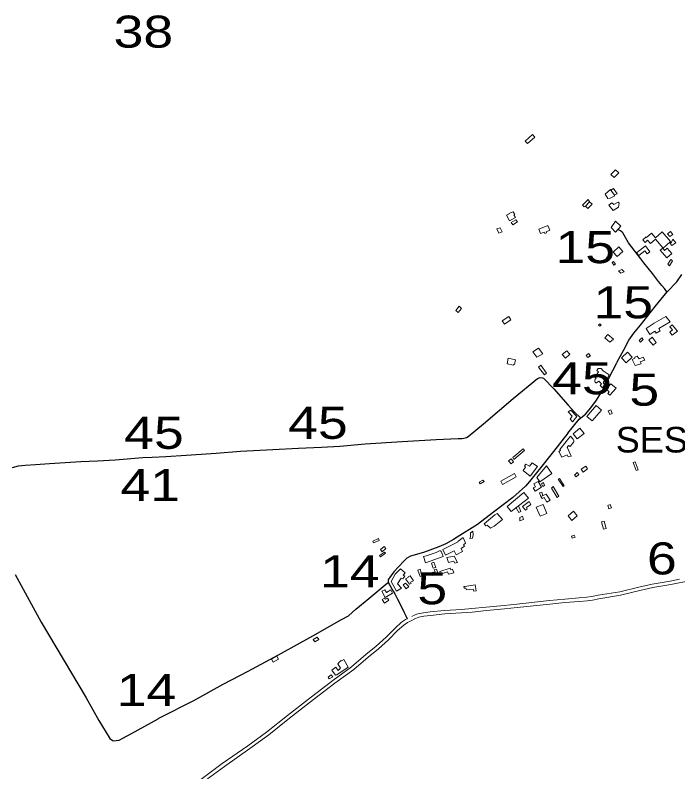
# Model space of a CAD drawing. Extents: x 476989 to 498418, y 4381813 to 4416555.
# Drawn here: x 484565 to 485599, y 4384627 to 4385808 of the extents above; entities that cross this region are included whole.
import ezdxf
from ezdxf.enums import TextEntityAlignment as Align

# ---------------------------------------------------------------- set-up
doc = ezdxf.new("R2010")
doc.units = 0
doc.header["$LTSCALE"] = 20
doc.linetypes.add('MEDIUM_DASHED', pattern=[4.5, 3, -1.5])
for name, color, linetype, lineweight in [('13', 7, 'Continuous', 13), ('36', 7, 'Continuous', 13), ('47', 7, 'Continuous', 13), ('48', 7, 'MEDIUM_DASHED', 13), ('6', 7, 'Continuous', 25)]:
    doc.layers.add(name, color=color, linetype=linetype, lineweight=lineweight)
doc.layers.add('7', color=7, linetype='Continuous')

msp = doc.modelspace()

# ---------------------------------------------------------------- linework, layer by layer
at = {"layer": '36'}
for points in [[(485422.62, 4384890.78), (485445.5, 4384892.7), (485457.67, 4384893.65), (485465.81, 4384894.8), (485475.68, 4384896.69), (485509.45, 4384902.29), (485539.74, 4384909.58), (485559.9, 4384914.32), (485587.94, 4384918.87), (485619.65, 4384925.47)], [(485422.69, 4384896.4), (485445.04, 4384898.28), (485457.06, 4384899.22), (485464.89, 4384900.34), (485474.69, 4384902.21), (485508.34, 4384907.79), (485538.44, 4384915.04), (485558.81, 4384919.82), (485586.93, 4384924.38), (485601.44, 4384927.38)], [(485183.89, 4384869.09), (485187.49, 4384870.96), (485193.57, 4384873.46), (485202.11, 4384874.97), (485212.4, 4384876.37), (485235.13, 4384878.7), (485261.36, 4384880.1), (485277.67, 4384881.57), (485300.11, 4384883.76), (485328.15, 4384886.54), (485347.71, 4384888.4), (485398.68, 4384894.02), (485422.69, 4384896.4)], [(484851.61, 4384605.75), (484891.48, 4384635.27), (484931.04, 4384662.95), (484960.7, 4384684.23), (484993.21, 4384710.28), (485030.75, 4384739.64), (485063.92, 4384764.85), (485093.47, 4384786.49), (485116.03, 4384805.54), (485131.93, 4384818.81), (485147.77, 4384832.69), (485161.73, 4384847.04), (485171.53, 4384855.86), (485177.07, 4384859.62), (485182.06, 4384861.97), (485189.79, 4384866.01), (485195.1, 4384868.19), (485202.95, 4384869.58), (485213.04, 4384870.95), (485235.55, 4384873.26), (485261.75, 4384874.66), (485278.18, 4384876.14), (485300.64, 4384878.33), (485328.67, 4384881.11), (485348.27, 4384882.97), (485399.25, 4384888.59), (485422.62, 4384890.78)], [(484707.31, 4384502.21), (484734.52, 4384522.99), (484765.58, 4384547.94), (484791.08, 4384567.66), (484812.71, 4384583.16), (484848.35, 4384610.12), (484888.3, 4384639.7), (484927.89, 4384667.41), (484957.41, 4384688.58), (484989.83, 4384714.56), (485027.43, 4384743.96), (485060.66, 4384769.23), (485090.09, 4384790.79), (485112.52, 4384809.73), (485128.38, 4384822.96), (485144.01, 4384836.66), (485157.94, 4384850.98), (485168.16, 4384860.16), (485174.35, 4384864.37), (485176.85, 4384865.55)]]:
    msp.add_lwpolyline(points, dxfattribs=at)
at = {"layer": '47'}
for p, q in [((485430.73, 4385278.66), (485429.6, 4385277.65)), ((485429.64, 4385279.89), (485430.73, 4385278.66)), ((485431.59, 4385150.48), (485427.01, 4385144.68))]:
    msp.add_line(p, q, dxfattribs=at)
for points in [[(485375.86, 4385617.36), (485364.42, 4385607.2), (485360.77, 4385611.28), (485372.16, 4385621.45)], [(485501.94, 4385566.31), (485494.71, 4385558.99), (485499.66, 4385554.11), (485506.89, 4385561.43)], [(485500.76, 4385525.8), (485493.57, 4385522.16), (485490.11, 4385521.53), (485485.71, 4385528.5), (485494.07, 4385535.43)], [(485461.45, 4385516.54), (485454.91, 4385509.66), (485458.68, 4385506.07), (485465.22, 4385512.95)], [(485491.39, 4385511.08), (485498.17, 4385502.8), (485506.43, 4385508.01), (485507.49, 4385514.15), (485506.17, 4385515.97), (485499.43, 4385512.02), (485496.02, 4385514.62)], [(485336.5, 4385486.96), (485331.77, 4385495.38), (485335.76, 4385497.44), (485335.29, 4385498.25), (485342.2, 4385500.73), (485344.58, 4385496.66), (485343.21, 4385496.15), (485345.76, 4385492.09)], [(485346.38, 4385488.49), (485348.86, 4385485.12), (485341.52, 4385480.52), (485338.96, 4385484.25)], [(485501.99, 4385486.17), (485494.94, 4385476.06), (485501.89, 4385468.84), (485509.91, 4385478.63)], [(485316.66, 4385474.25), (485319.79, 4385467.3), (485324.91, 4385469.72), (485321.65, 4385475.92)], [(485382.2, 4385473.84), (485385, 4385466.76), (485390.55, 4385468.79), (485391.34, 4385466.68), (485394.27, 4385468.09), (485393.65, 4385469.76), (485399.3, 4385472.35), (485396.43, 4385479.26)], [(485576.12, 4385444.28), (485564.24, 4385457.89), (485556.57, 4385451.2), (485551.89, 4385456.56), (485547.94, 4385453.11), (485544.46, 4385457.09), (485549.66, 4385461.64), (485550.29, 4385460.91), (485558.02, 4385467.59), (485564.31, 4385460.3), (485574.72, 4385469.29), (485587.69, 4385454.27)], [(485583.19, 4385466.47), (485586.58, 4385462.08), (485591.06, 4385465.53), (485587.67, 4385469.92)], [(485591.25, 4385458.17), (485589.16, 4385453.18), (485586.96, 4385451.48), (485589.53, 4385448.14), (485595.75, 4385452.26), (485594.06, 4385455.21)], [(485513.39, 4385438.88), (485504.37, 4385430.87), (485498, 4385438.05), (485507.02, 4385446.06)], [(485534.82, 4385436.85), (485548.41, 4385447.53), (485555.55, 4385438.42), (485551.49, 4385435.24), (485547.76, 4385439.99), (485538.35, 4385432.6)], [(485571.57, 4385440.75), (485581.68, 4385428.75), (485589.75, 4385435.55), (485582.63, 4385443.99), (485578.45, 4385440.47), (485575.5, 4385443.96)], [(485488.51, 4385430.38), (485490.9, 4385426.94), (485494.12, 4385429.18), (485491.73, 4385432.62)], [(485587.94, 4385426.11), (485583.51, 4385419.27), (485585.96, 4385416.4), (485590.99, 4385424.11)], [(485496.41, 4385421.49), (485499.18, 4385417.58), (485501.63, 4385419.31), (485498.86, 4385423.22)], [(485515.18, 4385406.96), (485509.98, 4385405.16), (485506.28, 4385408.67), (485511.49, 4385410.99)], [(485261.75, 4385350.07), (485256.55, 4385343.42), (485252.49, 4385346.53), (485257.99, 4385353.63)], [(485328.63, 4385325.22), (485324.86, 4385330.61), (485335.14, 4385337.31), (485338.56, 4385332.44)], [(485549.71, 4385318.83), (485561.98, 4385326.75), (485580.37, 4385337.6), (485587.23, 4385328.94), (485569.52, 4385318.84), (485571.72, 4385315.06), (485565.44, 4385311.55), (485563.46, 4385314.43), (485555.65, 4385309.29)], [(485477.4, 4385325.79), (485479.27, 4385324.15), (485477.42, 4385322.04), (485475.55, 4385323.68)], [(485590.08, 4385308.34), (485598.5, 4385314.38), (485590.16, 4385324.25), (485586.82, 4385321.45), (485590.88, 4385316.59), (485586.69, 4385312.74)], [(485498.45, 4385302.23), (485490, 4385309.55), (485485.17, 4385303.97), (485492.83, 4385297.33)], [(485542.75, 4385303.99), (485538.6, 4385300.17), (485540.85, 4385297.49), (485545.11, 4385301.63)], [(485559.04, 4385304.89), (485565.52, 4385297.05), (485560.45, 4385292.86), (485553.97, 4385300.7)], [(485379.07, 4385273.78), (485372.7, 4385282.19), (485381.81, 4385288.09), (485388.5, 4385279.35)], [(485345.88, 4385269.62), (485344.44, 4385262.34), (485343.13, 4385262.81), (485342.47, 4385261.32), (485332.59, 4385263.42), (485334.26, 4385272.11)], [(485462.96, 4385275.95), (485458.57, 4385273.46), (485455.91, 4385276.72), (485459.56, 4385279.6)], [(485520.66, 4385281.5), (485511.38, 4385272.95), (485518.48, 4385265.25), (485527.76, 4385273.8)], [(485535.88, 4385275.28), (485538.53, 4385271.26), (485545.24, 4385273.79), (485547.35, 4385269.41), (485540.18, 4385266.44), (485542.09, 4385263.63), (485532.37, 4385260.7), (485528.09, 4385270.51), (485532.09, 4385272.56), (485531.74, 4385273.91)], [(485385.42, 4385261.39), (485394.28, 4385248.91), (485391.08, 4385246.45), (485381.82, 4385258.29)], [(485491.87, 4385246.19), (485482.36, 4385252.63), (485479.41, 4385256.13), (485474.53, 4385256.42), (485472.69, 4385253.22), (485475.36, 4385251.23), (485469.68, 4385242.53), (485471.61, 4385240.93), (485470.02, 4385239.75), (485469.7, 4385238.63), (485469.68, 4385237.51), (485469.66, 4385235.93), (485469.95, 4385235.1), (485470.91, 4385233.81), (485472.33, 4385233.94), (485474.23, 4385235.19), (485476.05, 4385236.29), (485479.89, 4385232.48), (485477.67, 4385229.44), (485481.67, 4385225.85), (485484.68, 4385231.74), (485482.54, 4385233.72), (485485.91, 4385239.08), (485487.71, 4385238.75)], [(485502.9, 4385225.4), (485493.14, 4385214.36), (485489.67, 4385217.42), (485491.81, 4385219.85), (485487.35, 4385223.77), (485494.77, 4385232.21)], [(485471.75, 4385198.38), (485457.07, 4385181.29), (485465.18, 4385174.32), (485479.86, 4385191.41)], [(485494.31, 4385191.46), (485496.54, 4385186.14), (485492.79, 4385184.57), (485490.56, 4385189.89)], [(485446.33, 4385162.95), (485435.67, 4385154.43), (485442.19, 4385146.28), (485452.85, 4385154.8)], [(485341.54, 4385117.13), (485358, 4385131.01), (485359.88, 4385128.25), (485343.44, 4385114.36)], [(485335.12, 4385111.93), (485338.88, 4385107.2), (485342.55, 4385110.64), (485339.07, 4385115.06)], [(485357.51, 4385097.15), (485368.62, 4385088.17), (485380.36, 4385103.26), (485372.01, 4385109.03), (485367.56, 4385103.58), (485362.09, 4385107.01), (485359.66, 4385104.07), (485361.62, 4385102.4)], [(485532.7, 4385110.77), (485537.34, 4385098.3), (485534.08, 4385097.09), (485529.44, 4385109.56)], [(485379.23, 4385085.92), (485383.64, 4385079.14), (485402.54, 4385092.1), (485394.26, 4385104.11)], [(485444.62, 4385090.94), (485440.26, 4385087.1), (485437.78, 4385089.92), (485442.14, 4385093.76)], [(485458.4, 4385099.53), (485451.27, 4385094.65), (485448.34, 4385098.92), (485455.47, 4385103.8)], [(485290.74, 4385076.25), (485296.71, 4385079.76), (485295.04, 4385081.98), (485289.22, 4385078.94)], [(485346.7, 4385087.36), (485344.04, 4385092.2), (485323.12, 4385080.13), (485325.71, 4385075.16)], [(485414.69, 4385084.77), (485421.67, 4385073.34), (485420.02, 4385071.95), (485412.62, 4385083.7)], [(485376.42, 4385064.78), (485386.3, 4385071.05), (485380.99, 4385079.78), (485374.59, 4385076.18), (485377.22, 4385071.74), (485373.36, 4385069.71)], [(485386.27, 4385076.22), (485388.49, 4385071.93), (485391.18, 4385073.68), (485389.36, 4385078.3)], [(485401.88, 4385069.6), (485410.97, 4385054.66), (485413.3, 4385056.85), (485404.78, 4385072.14)], [(485332.83, 4385040.86), (485358.81, 4385062.46), (485366.1, 4385053.67), (485338.95, 4385033.1)], [(485400.09, 4385050.6), (485393.57, 4385059.83), (485385.55, 4385056.3), (485387.34, 4385053.1), (485390.5, 4385054.62), (485394.78, 4385047.66)], [(485356.66, 4385040.89), (485366.9, 4385048.44), (485369.63, 4385044), (485362.81, 4385039.04), (485363.91, 4385036.96), (485361.23, 4385035.02)], [(485378.19, 4385039.92), (485388.72, 4385044.18), (485394.8, 4385029.82), (485384.25, 4385025.7)], [(485489.62, 4385042.13), (485493.73, 4385043.77), (485495.65, 4385038.96), (485491.54, 4385037.32)], [(485317.22, 4385029.98), (485325.37, 4385020.45), (485312.51, 4385010.01), (485306.62, 4385006.83), (485301.81, 4385011.58), (485299.61, 4385010.55), (485296.92, 4385013.86), (485313.3, 4385027.75)], [(485356.54, 4385025.58), (485358.36, 4385020.59), (485352.67, 4385018.3), (485352.65, 4385023.86)], [(485436.15, 4385033.44), (485427.79, 4385026.2), (485433.84, 4385019.21), (485442.2, 4385026.45)], [(485483.95, 4385017.97), (485487.31, 4385006.49), (485483.24, 4385005.3), (485479.88, 4385016.78)], [(485275.35, 4384999.72), (485275.62, 4384993.72), (485274.51, 4384991.12), (485278.93, 4384991.49), (485279.63, 4384996.44), (485279.21, 4385002.07)], [(485131.88, 4384990.73), (485133.04, 4384987.96), (485124.38, 4384983.93), (485123.04, 4384986.67)], [(485232.24, 4384973.73), (485256.24, 4384985.71), (485255.64, 4384986.42), (485264.26, 4384992.64), (485267.98, 4384983.55), (485264.85, 4384980.92), (485265.96, 4384978.66), (485260.82, 4384975.22), (485262.98, 4384970.42), (485253.45, 4384965.37), (485249.92, 4384971.55), (485236.63, 4384965.07)], [(485434.27, 4384991.29), (485438.67, 4384992.73), (485437.56, 4384996.12), (485433.16, 4384994.68)], [(485134.96, 4384973.48), (485137.8, 4384970.26), (485143.62, 4384975.18), (485140.65, 4384978.64)], [(485135.13, 4384962.27), (485133.6, 4384964.2), (485141.49, 4384969.44), (485142.72, 4384967.81)], [(485202.26, 4384962.64), (485205.11, 4384952.88), (485232.87, 4384962.57), (485229.87, 4384971.23), (485228.85, 4384971.04), (485228.23, 4384972.06), (485221.76, 4384969.24), (485206.44, 4384963.71)], [(485241.19, 4384953.59), (485238.74, 4384961.16), (485249.91, 4384963.4), (485255.04, 4384953.22), (485251.01, 4384952.26), (485249.57, 4384955.39)], [(485218.26, 4384953.88), (485221.3, 4384945.37), (485217.52, 4384944.38), (485214.88, 4384952.63)], [(485166.54, 4384943.66), (485173.38, 4384937.5), (485170.74, 4384933.52), (485172.96, 4384932.16), (485170.02, 4384927.89), (485167.44, 4384928.93), (485161.73, 4384920.25), (485168.12, 4384913.52), (485160.35, 4384908.85), (485151.84, 4384923.7), (485158.04, 4384935.36)], [(485196.83, 4384931.59), (485193.55, 4384941.49), (485197.01, 4384942.93), (485198.74, 4384937.86), (485198.11, 4384937.64), (485199.61, 4384932.22)], [(485222.65, 4384942.91), (485225.26, 4384935.23), (485216.88, 4384932.94), (485215.88, 4384937.84), (485220.3, 4384938.94), (485219.08, 4384941.85)], [(485249.49, 4384937.5), (485241.12, 4384935.21), (485239.52, 4384938.69), (485228.76, 4384935.35), (485227.77, 4384939.36), (485244.05, 4384944.48), (485244.89, 4384942.19), (485247.54, 4384943.11)], [(485186.49, 4384924.62), (485181.37, 4384932.42), (485178.47, 4384930.93), (485178.71, 4384930.27), (485174.01, 4384928), (485180.62, 4384919.36), (485183.12, 4384920.9), (485181.75, 4384922.86)], [(485174.13, 4384921.38), (485179.41, 4384916.01), (485175.21, 4384912.35), (485170.29, 4384918.41)], [(485266.7, 4384916.2), (485282.71, 4384918.56), (485284.62, 4384909.24), (485280.59, 4384908.66), (485279.6, 4384911.79), (485269.14, 4384910.81), (485268.41, 4384913.55), (485265.87, 4384913.33), (485264.93, 4384915.83)], [(485142.63, 4384898.78), (485154.08, 4384905.6), (485151.02, 4384910.61), (485144.58, 4384906.61), (485141.69, 4384910.99), (485137.02, 4384908.61)], [(485137.57, 4384895.7), (485141.36, 4384889.94), (485148.18, 4384894.62), (485146.28, 4384897.8), (485142.69, 4384896.02), (485141.37, 4384897.6)], [(485038.74, 4384833.32), (485032.85, 4384829.56), (485030.27, 4384833.1), (485036.4, 4384836.94)], [(484964.87, 4384802.3), (484967.76, 4384797.99), (484976.23, 4384802.68), (484973.49, 4384807.16)], [(485077.7, 4384801.78), (485084.8, 4384790.17), (485067.22, 4384778.07), (485064.7, 4384777.53), (485059.16, 4384785.44), (485065.69, 4384789.96), (485068.86, 4384784.97), (485072.67, 4384788.24), (485068.78, 4384795.47), (485070.08, 4384796.6), (485069.91, 4384797.28), (485073.98, 4384800.36), (485074.47, 4384799.7)], [(485058.21, 4384777.93), (485060.61, 4384775.18), (485055.1, 4384771.73), (485053.37, 4384774.59)]]:
    msp.add_lwpolyline(points, close=True, dxfattribs=at)
for points in [[(485429.64, 4385279.89), (485426.15, 4385283.84), (485418.4, 4385278.2), (485423.65, 4385272.41), (485429.6, 4385277.65)], [(485427.86, 4385188.7), (485432.25, 4385191), (485441.64, 4385181.18)], [(485441.64, 4385181.18), (485434.85, 4385173.17), (485431, 4385177.06), (485434.44, 4385181.58), (485427.86, 4385188.36)], [(485427.01, 4385144.68), (485414.85, 4385130.05), (485416.09, 4385128.19), (485413.43, 4385126.89), (485418.24, 4385117.89), (485426.55, 4385121.28)], [(485426.79, 4385133.81), (485428.39, 4385136.27), (485430.92, 4385134.66), (485436.72, 4385141.78), (485436.75, 4385143.51), (485435.88, 4385145.77), (485431.59, 4385150.48)], [(485426.76, 4385132.14), (485426.34, 4385133.12), (485426.79, 4385133.81)], [(485426.55, 4385121.28), (485428.06, 4385118.42), (485432.65, 4385119.55), (485426.76, 4385132.14)], [(485385.55, 4385056.3), (485383.4, 4385062.17), (485386.75, 4385063.22), (485388.34, 4385057.54)], [(485350.4, 4385041.78), (485353.89, 4385032.82), (485350.82, 4385031.71), (485346.73, 4385039)]]:
    msp.add_lwpolyline(points, dxfattribs=at)
at = {"layer": '48'}
for points in [[(485494.62, 4385534.65), (485498.59, 4385537.17), (485504.3, 4385529.07), (485499.88, 4385527.08)], [(485462.03, 4385516), (485459.32, 4385519.8), (485450.49, 4385510.99), (485453.01, 4385508.33), (485455.17, 4385509.42)]]:
    msp.add_lwpolyline(points, dxfattribs=at)
at = {"layer": '6'}
for points in [[(485582.1, 4385375.98), (485578.17, 4385381.31), (485574, 4385385.61), (485568.72, 4385391.95), (485559.52, 4385404.75), (485546.16, 4385421.17), (485541.55, 4385427.29), (485522.24, 4385452.62), (485513.26, 4385467.74), (485512.2, 4385468.93), (485509.6, 4385470.94), (485505.65, 4385473.38)], [(485504.14, 4385265.76), (485509.89, 4385275.82), (485514.92, 4385285.15), (485522.59, 4385300.57), (485530.19, 4385311.59), (485540.73, 4385324.04), (485546.48, 4385331.36), (485563.74, 4385352.91), (485582.43, 4385376.13), (485597.52, 4385391.7), (485605.43, 4385403.19)], [(485427.21, 4385155.18), (485445.15, 4385177.06), (485454.85, 4385185.2), (485463.48, 4385194.77), (485472.34, 4385206.98), (485479.05, 4385217.52), (485485.93, 4385229.85), (485497.43, 4385253.31), (485504.14, 4385265.28)], [(484721.33, 4385113.65), (484764.31, 4385117.19), (484778.74, 4385117.71), (484800.28, 4385118.92), (484831.98, 4385121), (484878.85, 4385124.3), (484916.93, 4385127.45), (484967.4, 4385129.79), (485007.23, 4385131.89), (485042.9, 4385133.62), (485071.57, 4385135.19), (485111.25, 4385138.74), (485168.74, 4385142.21), (485221.87, 4385145.3), (485256.19, 4385146.79), (485262.58, 4385146.84), (485265.43, 4385147.4), (485269.18, 4385148.39), (485271.82, 4385150.33), (485295.88, 4385169.82), (485342.32, 4385209.37), (485380.09, 4385240.53), (485384.25, 4385242.18), (485388.13, 4385241.7), (485389.63, 4385241.04), (485389.91, 4385240.71), (485405.62, 4385224.4), (485428.07, 4385199.13)], [(485447.21, 4385179.34), (485437.95, 4385187.81), (485428.09, 4385199.1), (485428.07, 4385199.13)], [(485427.21, 4385155.18), (485405.21, 4385126.89), (485382.59, 4385098.77), (485367.56, 4385079.71), (485361.63, 4385072.41), (485341.83, 4385055.04), (485311.5, 4385032.01), (485286.65, 4385012.95), (485254.81, 4384992.98), (485249.03, 4384989.33), (485237.16, 4384982.81), (485226.33, 4384977.63), (485202.03, 4384968.94), (485181.81, 4384963.08), (485176.45, 4384960.11), (485171.5, 4384955.6), (485155.92, 4384938.89), (485147.88, 4384927.31), (485147.13, 4384926), (485147.27, 4384922.29), (485148.81, 4384919.8), (485155.15, 4384908.42), (485157.31, 4384904.48), (485161.8, 4384896.09), (485168.3, 4384883.05), (485171.89, 4384875.57), (485174.86, 4384870), (485176.85, 4384865.55)], [(484560.92, 4385101.66), (484570.5, 4385104.22), (484580.6, 4385105.21), (484596.61, 4385106.51), (484618.44, 4385108.14), (484667.62, 4385110.91), (484693.66, 4385111.99), (484721.33, 4385113.65)], [(484565.32, 4384934.84), (484605.7, 4384860.08), (484675.78, 4384741.99), (484695.63, 4384706.66), (484712.65, 4384678.75), (484716.37, 4384675.91), (484718.11, 4384675.18), (484727.45, 4384676.03), (484733.24, 4384679.19), (484746.86, 4384686.49), (484788.02, 4384709.66)], [(484788.22, 4384709.74), (484790.05, 4384710.77), (484843.73, 4384738.03), (484889.45, 4384763.36), (484928.92, 4384783.99), (484975.95, 4384809.37), (485029.5, 4384838.87), (485074.04, 4384864.28), (485084.96, 4384870.3), (485091.46, 4384875.82), (485096.64, 4384880.61), (485117.13, 4384897.31), (485145.79, 4384921.2), (485147.48, 4384921.96)]]:
    msp.add_lwpolyline(points, dxfattribs=at)

# ---------------------------------------------------------------- texts
at = {"layer": '13', "width": 1.25}
for s, p in [('38', (484765.19, 4385757.02)), ('15', (485454.61, 4385420.63)), ('15', (485514.01, 4385334.51)), ('45', (485449.56, 4385216)), ('5', (485546.77, 4385198.14)), ('45', (485037.56, 4385146.41)), ('45', (484781.71, 4385130.81)), ('41', (484775.97, 4385049.16)), ('6', (485574.19, 4384934.8)), ('14', (485087.35, 4384914.55)), ('5', (485215.97, 4384888.23)), ('14', (484770.01, 4384729.3))]:
    msp.add_text(s, height=50, dxfattribs=at).set_placement(p, align=Align.CENTER)
at = {"layer": '7', "width": 1.05}
msp.add_text('SES OLLERIES', height=40, dxfattribs=at).set_placement((485703.59, 4385125.11), align=Align.CENTER)

doc.saveas('drawing.dxf')
